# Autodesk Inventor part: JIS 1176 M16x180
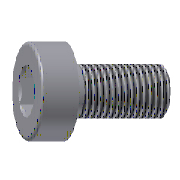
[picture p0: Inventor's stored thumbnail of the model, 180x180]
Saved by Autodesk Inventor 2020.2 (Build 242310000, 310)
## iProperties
Manager: www.cadconsulting.pl
Company: Fabian Stasiak CAD Consulting
Created: 2014-02
Part Number: JIS 1176 M16x180
Material: Stal, miękka
Description: Cylinder Head Cap Screw
Document SubType Name: Modeling
Designer: F.Stasiak
Standard Revision: 1
Language: pl-PL
Size Designation: M16x180
Categories: <MemberInstance><Categories><Category DisplayName="Forma wtryskowa" InternalName="349578f2-f4d4-4954-8c09-8e99297a61c0" Mnemonic="MOLD"><Category DisplayName="C
Mass: 0.133121 g
Surface Area: 2.01441 cm^2
Volume: 0.133121 cm^3
Density: 7.85 g/cm^3
Appearance: Częściowo polerowana
Catalog Web Link: www.expertbooks.pl
IsCustomPart: 0
Author: F.Stasiak
Subject: Zbiór ćwiczeń. Autodesk Inventor 2020. Kurs Professional
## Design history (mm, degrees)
sketch "Sketch1"
  geometry: L1 (0, -219.2)-(0, 55.2) reference; L2 (8.083, 16)-(12, 16); L3 (12, 16)-(12, 0); L4 (12, 0)-(8, 0); L5 (8, 0)-(8, -180); L6 (8, -180)-(0, -180); L7 (0, 3.794)-(0, -180); L8 (0, 3.794)-(7, 8); L9 (7, 8)-(7, 14.917); L10 (7, 14.917)-(8.083, 16); 1 further point
  constraints: 18 end point, 4 vertical, 3 horizontal, 2 point on line
  dimensions: "d0" = 24 diameter of L3 L1 (= dk); "d1" = 16 distance between parallel lines of L4 L2 (= k); "d2" = 16 diameter of L5 L1 (= d); "d3" = 180 distance between parallel lines of L6 L4 (= L); "d4" = 59 deg angle of L1 L8; "d5" = 45 deg angle of L1 L10; "d6" = 14 diameter of L9 L1 (= sw); "d7" = 16.16581 diameter of L2.start L1 (= 1.1547 x sw); "d8" = 8 distance from line of L8.end L2 (= t)
revolve "Revolution1" sketch "Sketch1" stored, may be unused: angle "d44" = 90 deg
sketch "Sketch2"
  geometry: L1 (0, 8.083)-(7, 4.041); L2 (7, 4.041)-(7, -4.041); L3 (7, -4.041)-(0, -8.083); L4 (0, -8.083)-(-7, -4.041); L5 (-7, -4.041)-(-7, 4.041); L6 (-7, 4.041)-(0, 8.083); 3 further points
  constraints: 12 end point, 2 vertical alignment, 1 coincident, 14 other
extrude "Extrusion1" cut sketch "Sketch2" taper "d9" = 0 deg; stored distance "d45" = 10
thread "Thread1" dims "d10" = 44 (= b), "d11" = 0
chamfer "Chamfer1" distance "d12" = 1 (= 0.5 x P); stored, may be unused: second distance "d50" = 2, angle "d51" = 45 deg
fillet "Fillet1" dims "d13" = 1 (= 0.5 x P)
body "Solid1"
other parameters: "d" = 16 [user parameter; used in 1 equation term], "L" = 180 [user parameter; used in 1 equation term], "dk" = 24 [user parameter; used in 1 equation term], "b" = 44 [user parameter; used in 1 equation term], "k" = 16 [user parameter; used in 1 equation term], "sw" = 14 [user parameter; used in 2 equation terms], "t" = 8 [user parameter; used in 1 equation term], "P" = 2 [user parameter; used in 2 equation terms], "d14" = 0, "d15" = 0, "d55" = 0
